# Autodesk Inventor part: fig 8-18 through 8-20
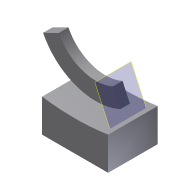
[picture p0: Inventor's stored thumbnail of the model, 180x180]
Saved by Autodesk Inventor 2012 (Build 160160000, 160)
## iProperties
Created: 2010-03
Part Number: fig 8-18 through 8-20
Document SubType Name: Modeling
Designer: CADSoft
Density: 1 g/cm^3
Material: Default
Author: CADSoft
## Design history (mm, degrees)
sketch "Sketch1"
  geometry: A1 r 30.196 centre (0, 36.902) between (-12.551, 9.437) and (27.083, 23.549); 1 further point
  constraints: 2 point on circle, 1 centre point
sketch "Sketch2"
  geometry: L1 (-20, -19.986)-(20, -19.986); L2 (20, -19.986)-(20, -0.051); L3 (-20, 0.014)-(-20, -19.986); A1 r 135 centre (0.218, 133.492) between (-20, 0.014) and (20, -0.051); 1 further point
  constraints: 6 end point, 2 point on circle, 1 centre point, 1 horizontal, 1 parallel, 1 perpendicular
extrude "Extrusion1" new body sketch "Sketch2" stored distance "d9" = 30; taper "d10" = 0 deg
workplane "Work Plane2"
sketch "Sketch4"
  geometry: L1 (2.42, -5.432)-(-3.367, -5.432); L2 (-3.367, -5.432)-(-3.367, 5.234); L3 (-3.367, 5.234)-(2.42, 5.234); L4 (2.42, 5.234)-(2.42, -5.432); 1 further point
  constraints: 8 end point, 2 parallel, 1 horizontal, 1 perpendicular
sweep "Sweep3" sketch "Sketch4" dims "d13" = 0
body "Solid1"
